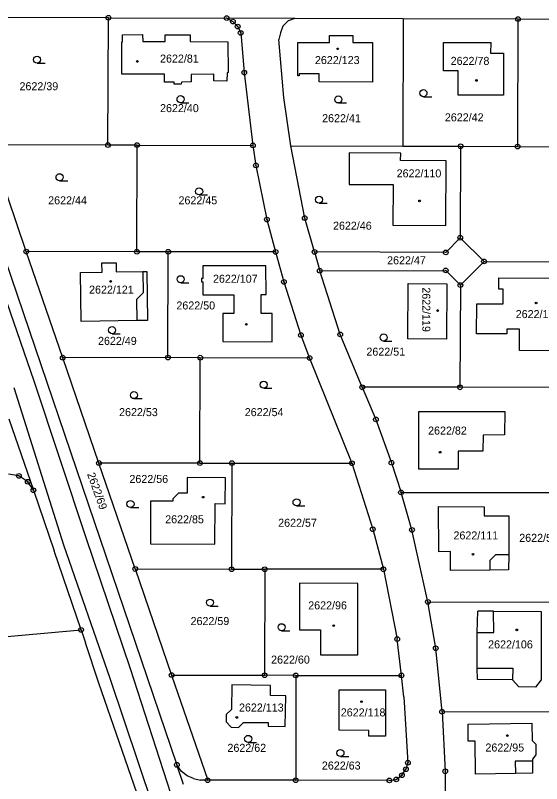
# Model space of a CAD drawing. Extents: x -736345 to -729997, y -1130177 to -1122501.
# Drawn here: x -734114.7 to -734002.9, y -1125902.8 to -1125739.6 of the extents above; entities that cross this region are included whole.
import ezdxf

# ---------------------------------------------------------------- set-up
doc = ezdxf.new("R2010")
doc.units = 0
for name, color, linetype in [('Vrstva 1', 7, 'Continuous'), ('Vrstva 18', 7, 'Continuous'), ('Vrstva 19', 7, 'Continuous'), ('Vrstva 25', 7, 'Continuous'), ('Vrstva 4', 7, 'Continuous')]:
    doc.layers.add(name, color=color, linetype=linetype)

msp = doc.modelspace()

# ---------------------------------------------------------------- linework, layer by layer
at = {"layer": 'Vrstva 1'}
for points in [[(-734094.92, -1125740.08), (-734126.23, -1125740.04)], [(-734095.04, -1125767.14), (-734094.92, -1125740.08)], [(-734094.92, -1125740.08), (-734069.81, -1125740.16)], [(-734069.81, -1125740.16), (-734068.48, -1125740.89)], [(-734055.33, -1125740.27), (-734069.81, -1125740.16)], [(-734055.33, -1125740.27), (-734056.77, -1125740.73)], [(-734032.34, -1125740.31), (-734055.33, -1125740.27)], [(-734032.34, -1125740.31), (-734032.38, -1125767.38)], [(-734007.98, -1125740.37), (-734032.34, -1125740.31)], [(-734007.98, -1125740.37), (-734008.04, -1125767.45)], [(-733971.15, -1125740.43), (-734007.98, -1125740.37)], [(-734068.48, -1125740.89), (-734067.48, -1125741.97)], [(-734067.48, -1125741.97), (-734066.84, -1125743.32)], [(-734057.87, -1125741.84), (-734058.39, -1125743.27)], [(-734056.77, -1125740.73), (-734057.87, -1125741.84)], [(-734066.84, -1125743.32), (-734066.08, -1125751.74)], [(-734058.39, -1125743.27), (-734058.72, -1125744.74)], [(-734092.08, -1125752.08), (-734092.09, -1125745.18)], [(-734092.09, -1125745.18), (-734091.9, -1125745.18)], [(-734091.9, -1125743.7), (-734087.66, -1125743.66)], [(-734091.9, -1125745.18), (-734091.9, -1125743.7)], [(-734087.66, -1125743.66), (-734087.63, -1125745.15)], [(-734087.63, -1125745.15), (-734082.89, -1125745.15)], [(-734082.89, -1125745.15), (-734082.89, -1125743.7)], [(-734082.89, -1125743.7), (-734077.59, -1125743.71)], [(-734077.59, -1125743.71), (-734077.6, -1125745.15)], [(-734077.6, -1125745.15), (-734069.54, -1125745.18)], [(-734069.54, -1125745.18), (-734069.49, -1125751.72)], [(-734057.69, -1125757.02), (-734058.72, -1125744.74)], [(-734047.96, -1125745.32), (-734047.96, -1125743.86)], [(-734047.96, -1125743.86), (-734043.05, -1125743.87)], [(-734043.05, -1125743.87), (-734043.05, -1125745.34)], [(-734054.69, -1125752.41), (-734054.69, -1125745.32)], [(-734054.69, -1125745.32), (-734047.96, -1125745.32)], [(-734043.05, -1125745.34), (-734038.84, -1125745.35)], [(-734038.84, -1125745.35), (-734038.85, -1125753.75)], [(-734023.8, -1125751.34), (-734023.78, -1125745.33)], [(-734023.78, -1125745.33), (-734013.76, -1125745.36)], [(-734013.76, -1125745.36), (-734013.77, -1125747.59)], [(-734131.94, -1125747.29), (-734080.38, -1125898.82)], [(-734013.77, -1125747.59), (-734011.03, -1125747.62)], [(-734011.03, -1125747.62), (-734011.05, -1125756.51)], [(-734069.72, -1125751.78), (-734069.75, -1125753.53)], [(-734069.49, -1125751.72), (-734069.72, -1125751.78)], [(-734066.08, -1125751.74), (-734064.26, -1125767.2)], [(-734020.69, -1125751.34), (-734023.8, -1125751.34)], [(-734020.68, -1125756.52), (-734020.69, -1125751.34)], [(-734083.04, -1125752.1), (-734092.08, -1125752.08)], [(-734083.03, -1125753.74), (-734083.04, -1125752.1)], [(-734077.36, -1125752.11), (-734077.37, -1125753.72)], [(-734072.55, -1125752.1), (-734077.36, -1125752.11)], [(-734072.56, -1125753.52), (-734072.55, -1125752.1)], [(-734054.41, -1125752.41), (-734054.69, -1125752.41)], [(-734050.19, -1125752.03), (-734054.41, -1125752.02)], [(-734054.41, -1125752.02), (-734054.41, -1125752.41)], [(-734050.19, -1125753.72), (-734050.19, -1125752.03)], [(-734080.96, -1125753.8), (-734083.03, -1125753.74)], [(-734080.96, -1125754.22), (-734080.96, -1125753.8)], [(-734079.46, -1125754.23), (-734080.96, -1125754.22)], [(-734079.42, -1125753.75), (-734079.46, -1125754.23)], [(-734077.37, -1125753.72), (-734079.42, -1125753.75)], [(-734069.75, -1125753.53), (-734072.56, -1125753.52)], [(-734038.85, -1125753.75), (-734050.19, -1125753.72)], [(-734011.05, -1125756.51), (-734020.68, -1125756.52)], [(-734056.17, -1125767.33), (-734057.69, -1125757.02)], [(-734112.36, -1125789.78), (-734120.11, -1125767.1)], [(-734095.04, -1125767.14), (-734120.11, -1125767.1)], [(-734088.85, -1125767.14), (-734095.04, -1125767.14)], [(-734088.88, -1125789.81), (-734088.85, -1125767.14)], [(-734088.85, -1125767.14), (-734064.26, -1125767.2)], [(-734064.26, -1125767.2), (-734063.62, -1125771.46)], [(-734053.24, -1125782.65), (-734056.17, -1125767.33)], [(-734056.17, -1125767.33), (-734032.38, -1125767.38)], [(-734032.38, -1125767.38), (-734020.17, -1125767.4)], [(-734020.17, -1125767.4), (-734020.23, -1125786.83)], [(-734020.17, -1125767.4), (-734008.04, -1125767.45)], [(-734008.04, -1125767.45), (-733957.96, -1125767.5)], [(-734043.78, -1125768.77), (-734043.82, -1125775.5)], [(-734032.87, -1125768.84), (-734043.78, -1125768.77)], [(-734032.88, -1125770.45), (-734032.87, -1125768.84)], [(-734023.18, -1125770.51), (-734032.88, -1125770.45)], [(-734023.28, -1125784.24), (-734023.18, -1125770.51)], [(-734063.62, -1125771.46), (-734061.27, -1125782.97)], [(-734043.82, -1125775.5), (-734034.48, -1125775.54)], [(-734034.48, -1125775.54), (-734034.51, -1125784.17)], [(-734051.16, -1125789.83), (-734053.24, -1125782.65)], [(-734061.27, -1125782.97), (-734059.43, -1125789.83)], [(-734034.51, -1125784.17), (-734023.28, -1125784.24)], [(-734020.23, -1125786.83), (-734023.3, -1125789.96)], [(-734015.18, -1125791.87), (-734020.23, -1125786.83)], [(-734104.63, -1125812.31), (-734112.36, -1125789.78)], [(-734088.88, -1125789.81), (-734112.36, -1125789.78)], [(-734082.23, -1125789.81), (-734088.88, -1125789.81)], [(-734082.28, -1125812.3), (-734082.23, -1125789.81)], [(-734059.43, -1125789.83), (-734082.23, -1125789.81)], [(-734059.43, -1125789.83), (-734057.66, -1125796.21)], [(-734023.3, -1125789.96), (-734051.16, -1125789.83)], [(-734051.16, -1125789.83), (-734050.04, -1125793.83)], [(-734100.71, -1125804.59), (-734100.85, -1125794.18), (-734096.28, -1125794.13), (-734096.31, -1125792.18), (-734093.29, -1125792.13), (-734093.26, -1125794.08), (-734087.63, -1125794.01)], [(-734020.19, -1125796.89), (-734015.18, -1125791.87)], [(-734015.18, -1125791.87), (-733965.42, -1125792.05)], [(-734087.63, -1125794.01), (-734086.8, -1125794), (-734086.64, -1125804.4), (-734088.87, -1125804.42)], [(-734061.47, -1125792.78), (-734074.88, -1125792.79)], [(-734074.88, -1125792.79), (-734074.88, -1125795.51)], [(-734061.46, -1125798.9), (-734061.47, -1125792.78)], [(-734050.04, -1125793.83), (-734023.32, -1125793.78)], [(-734045.7, -1125807.38), (-734050.04, -1125793.83)], [(-734023.32, -1125793.78), (-734020.19, -1125796.89)], [(-734074.88, -1125795.51), (-734075.13, -1125795.51)], [(-734075.13, -1125795.51), (-734075.13, -1125796.22)], [(-734012.05, -1125797.76), (-734012.04, -1125795.38)], [(-734012.04, -1125795.38), (-733995.71, -1125795.44)], [(-734075.13, -1125796.22), (-734074.88, -1125796.22)], [(-734074.88, -1125796.22), (-734074.88, -1125798.93)], [(-734057.66, -1125796.21), (-734054.04, -1125807.5)], [(-734023.05, -1125796.61), (-734023.14, -1125808.35), (-734031.35, -1125808.28), (-734031.29, -1125796.54), (-734023.05, -1125796.61)], [(-734020.19, -1125796.89), (-734020.28, -1125818.61)], [(-734074.88, -1125798.93), (-734068.31, -1125798.94)], [(-734068.31, -1125798.94), (-734068.31, -1125802.96)], [(-734062.5, -1125802.96), (-734062.5, -1125798.9)], [(-734062.5, -1125798.9), (-734061.46, -1125798.9)], [(-734011.1, -1125797.76), (-734012.05, -1125797.76)], [(-734011.11, -1125800.88), (-734011.1, -1125797.76)], [(-734016.74, -1125807.24), (-734016.71, -1125800.86)], [(-734016.71, -1125800.86), (-734011.11, -1125800.88)], [(-734068.31, -1125802.96), (-734070.61, -1125802.95)], [(-734070.61, -1125802.95), (-734070.6, -1125808.89)], [(-734060.18, -1125802.94), (-734062.5, -1125802.96)], [(-734060.18, -1125808.91), (-734060.18, -1125802.94)], [(-734088.87, -1125804.42), (-734100.71, -1125804.59)], [(-734010.37, -1125807.27), (-734016.74, -1125807.24)], [(-734007.63, -1125806.28), (-734010.37, -1125806.27)], [(-734010.37, -1125806.27), (-734010.37, -1125807.27)], [(-734007.65, -1125810.78), (-734007.63, -1125806.28)], [(-734070.6, -1125808.89), (-734060.18, -1125808.91)], [(-734054.04, -1125807.5), (-734052.2, -1125812.38)], [(-734041.02, -1125818.61), (-734045.7, -1125807.38)], [(-733993.77, -1125810.83), (-734007.65, -1125810.78)], [(-734082.28, -1125812.3), (-734104.63, -1125812.31)], [(-734096.94, -1125834.69), (-734104.63, -1125812.31)], [(-734075.44, -1125812.31), (-734082.28, -1125812.3)], [(-734075.48, -1125834.72), (-734075.44, -1125812.31)], [(-734052.2, -1125812.38), (-734075.44, -1125812.31)], [(-734052.2, -1125812.38), (-734043.22, -1125834.75)], [(-734020.28, -1125818.61), (-734041.02, -1125818.61)], [(-734041.02, -1125818.61), (-734038.12, -1125825.44)], [(-733973.75, -1125818.73), (-734020.28, -1125818.61)], [(-734029.04, -1125823.75), (-734010.77, -1125823.72)], [(-734029.04, -1125836.03), (-734029.04, -1125823.75)], [(-734010.77, -1125823.72), (-734010.8, -1125828.74)], [(-734116.04, -1125825.31), (-734110.85, -1125840.49)], [(-734038.12, -1125825.44), (-734034.83, -1125834.64)], [(-734015.39, -1125828.77), (-734015.43, -1125832.14)], [(-734010.8, -1125828.74), (-734015.39, -1125828.77)], [(-734020.65, -1125832.14), (-734020.67, -1125836.01)], [(-734015.43, -1125832.14), (-734020.65, -1125832.14)], [(-734089.23, -1125857.21), (-734096.94, -1125834.69)], [(-734075.48, -1125834.72), (-734096.94, -1125834.69)], [(-734075.48, -1125834.72), (-734068.71, -1125834.7)], [(-734068.71, -1125834.7), (-734068.76, -1125857.26)], [(-734068.71, -1125834.7), (-734043.22, -1125834.75)], [(-734043.22, -1125834.75), (-734038.8, -1125848.75)], [(-734034.83, -1125834.64), (-734032.8, -1125840.94)], [(-734020.67, -1125836.01), (-734029.04, -1125836.03)], [(-734113.92, -1125837.42), (-734116.13, -1125837.03)], [(-734112.05, -1125838.66), (-734113.92, -1125837.42)], [(-734078.21, -1125837.79), (-734078.22, -1125841.09)], [(-734070.08, -1125837.82), (-734078.21, -1125837.79)], [(-734070.1, -1125843.33), (-734070.08, -1125837.82)], [(-734110.85, -1125840.49), (-734112.05, -1125838.66)], [(-734110.85, -1125840.49), (-734106.44, -1125853.38)], [(-734080.04, -1125841.1), (-734081.22, -1125842.29)], [(-734078.22, -1125841.09), (-734080.04, -1125841.1)], [(-734030.47, -1125848.91), (-734032.8, -1125840.94)], [(-734032.8, -1125840.94), (-733996.71, -1125840.98)], [(-734081.22, -1125842.78), (-734086.02, -1125842.78)], [(-734086.02, -1125842.78), (-734086, -1125851.89)], [(-734081.22, -1125842.29), (-734081.22, -1125842.78)], [(-734072.32, -1125851.91), (-734072.28, -1125843.32)], [(-734072.28, -1125843.32), (-734070.1, -1125843.33)], [(-734024.82, -1125843.96), (-734015.13, -1125844)], [(-734024.78, -1125853.55), (-734024.82, -1125843.96)], [(-734015.13, -1125844), (-734015.13, -1125845.89)], [(-734015.13, -1125845.89), (-734009.92, -1125845.91)], [(-734009.92, -1125845.91), (-734009.94, -1125854.22)], [(-734038.8, -1125848.75), (-734036.53, -1125857.28)], [(-734027.09, -1125864.2), (-734030.47, -1125848.91)], [(-734086, -1125851.89), (-734072.32, -1125851.91)], [(-734100.71, -1125870.15), (-734106.44, -1125853.38)], [(-734022.29, -1125853.52), (-734024.78, -1125853.55)], [(-734022.3, -1125857.52), (-734022.29, -1125853.52)], [(-734009.94, -1125854.22), (-734010.01, -1125857.42)], [(-734089.23, -1125857.21), (-734068.76, -1125857.26)], [(-734089.23, -1125857.21), (-734081.5, -1125879.74)], [(-734068.76, -1125857.26), (-734061.72, -1125857.27)], [(-734061.72, -1125857.27), (-734061.75, -1125879.79)], [(-734036.53, -1125857.28), (-734061.72, -1125857.27)], [(-734036.53, -1125857.28), (-734033.61, -1125872.11)], [(-734013.94, -1125857.49), (-734022.3, -1125857.52)], [(-734010.01, -1125857.42), (-734013.94, -1125857.49)], [(-734054.33, -1125860.23), (-734054.35, -1125870.14)], [(-734041.95, -1125860.26), (-734054.33, -1125860.23)], [(-734041.98, -1125875.42), (-734041.95, -1125860.26)], [(-734025.43, -1125874.05), (-734027.09, -1125864.2)], [(-734027.09, -1125864.2), (-733996.41, -1125864.26)], [(-734016.6, -1125870.68), (-734016.51, -1125866.17)], [(-734013.19, -1125866.2), (-734016.51, -1125866.17)], [(-734013.19, -1125866.2), (-734003.05, -1125866.23)], [(-734003.05, -1125866.23), (-734003.01, -1125880.79)], [(-734151.91, -1125874.75), (-734100.71, -1125870.15)], [(-734100.71, -1125870.15), (-734099.77, -1125872.89)], [(-734054.35, -1125870.14), (-734049.91, -1125870.14)], [(-734049.91, -1125870.14), (-734049.91, -1125875.42)], [(-734016.6, -1125878.29), (-734016.6, -1125870.68)], [(-734032.71, -1125879.82), (-734033.61, -1125872.11)], [(-734096.95, -1125881.49), (-734099.77, -1125872.89)], [(-734024.09, -1125887.55), (-734025.43, -1125874.05)], [(-734049.91, -1125875.42), (-734041.98, -1125875.42)], [(-734016.58, -1125880.72), (-734016.6, -1125878.29)], [(-734081.5, -1125879.74), (-734061.75, -1125879.79)], [(-734081.5, -1125879.74), (-734073.85, -1125902.09)], [(-734055.14, -1125879.81), (-734061.75, -1125879.79)], [(-734055.14, -1125879.81), (-734055.15, -1125902.09)], [(-734055.14, -1125879.81), (-734032.71, -1125879.82)], [(-734032.19, -1125884.35), (-734032.71, -1125879.82)], [(-734009.14, -1125880.73), (-734016.58, -1125880.72)], [(-734007.82, -1125882.27), (-734009.14, -1125880.73)], [(-734086.35, -1125912.11), (-734096.95, -1125881.49)], [(-734068.74, -1125881.79), (-734068.82, -1125887.04)], [(-734060.48, -1125881.95), (-734068.74, -1125881.79)], [(-734060.52, -1125884.12), (-734060.48, -1125881.95)], [(-734004.22, -1125882.3), (-734007.82, -1125882.27)], [(-734003.01, -1125880.79), (-734004.22, -1125882.3)], [(-734045.95, -1125882.86), (-734036.09, -1125882.87), (-734036.09, -1125892.71), (-734039.61, -1125892.72), (-734039.62, -1125891.5), (-734045.95, -1125891.48), (-734045.95, -1125882.86)], [(-734057.26, -1125884.16), (-734060.52, -1125884.12)], [(-734057.38, -1125890.67), (-734057.26, -1125884.16)], [(-734032.19, -1125884.35), (-734031.34, -1125898.37)], [(-734068.82, -1125887.04), (-734069.91, -1125888.13)], [(-734069.91, -1125888.13), (-734069.93, -1125889.69)], [(-734024.09, -1125887.55), (-733991.66, -1125887.51)], [(-734024.09, -1125887.55), (-734023.41, -1125900.2)], [(-734069.93, -1125889.69), (-734068.85, -1125890.81)], [(-734067.28, -1125890.88), (-734066.23, -1125889.83)], [(-734066.23, -1125889.83), (-734061.03, -1125889.86)], [(-734061.03, -1125889.86), (-734061.04, -1125890.62)], [(-734018.57, -1125890.15), (-734005.02, -1125889.98)], [(-734018.52, -1125893.76), (-734018.57, -1125890.15)], [(-734005.02, -1125889.98), (-734004.97, -1125893.67)], [(-734068.85, -1125890.81), (-734067.28, -1125890.88)], [(-734061.04, -1125890.62), (-734057.38, -1125890.67)], [(-734017.09, -1125893.79), (-734018.52, -1125893.76)], [(-734016.97, -1125900.78), (-734017.09, -1125893.79)], [(-734004.97, -1125893.67), (-734004.19, -1125894.42)], [(-734004.19, -1125894.42), (-734004.18, -1125896.69)], [(-734004.18, -1125896.69), (-734004.88, -1125897.63)], [(-734031.34, -1125898.37), (-734031.77, -1125899.76)], [(-734004.88, -1125898.05), (-734004.91, -1125900.57)], [(-734004.88, -1125897.63), (-734004.88, -1125898.05)], [(-734078.96, -1125903), (-734080.38, -1125898.82)], [(-734079.4, -1125900.21), (-734080.38, -1125898.82)], [(-734078.19, -1125901.14), (-734079.4, -1125900.21)], [(-734032.6, -1125901.04), (-734031.77, -1125899.76)], [(-734023.41, -1125900.2), (-734023.46, -1125910.4)], [(-734076.83, -1125901.75), (-734078.19, -1125901.14)], [(-734076.83, -1125901.75), (-734075.38, -1125902.06)], [(-734035.27, -1125902.13), (-734033.81, -1125901.92)], [(-734033.81, -1125901.92), (-734032.6, -1125901.04)], [(-734008.5, -1125900.63), (-734016.97, -1125900.78)], [(-734004.91, -1125900.57), (-734008.5, -1125900.63)], [(-734073.85, -1125902.09), (-734075.38, -1125902.06)], [(-734055.15, -1125902.09), (-734073.85, -1125902.09)], [(-734035.27, -1125902.13), (-734055.15, -1125902.09)]]:
    msp.add_lwpolyline(points, dxfattribs=at)
at = {"layer": 'Vrstva 25'}
for points in [[(-734110.07, -1125749.74), (-734108.32, -1125749.74)], [(-734079.6, -1125758.14), (-734077.85, -1125758.14)], [(-734046.1, -1125758.19), (-734044.35, -1125758.19)], [(-734028.04, -1125756.86), (-734026.29, -1125756.86)], [(-734105.29, -1125774.72), (-734103.54, -1125774.72)], [(-734075.66, -1125777.73), (-734073.91, -1125777.73)], [(-734050.21, -1125779.49), (-734048.46, -1125779.49)], [(-734079.58, -1125796.39), (-734077.83, -1125796.39)], [(-734094.15, -1125807.21), (-734092.4, -1125807.21)], [(-734036.5, -1125808.77), (-734034.75, -1125808.77)], [(-734061.96, -1125818.8), (-734060.21, -1125818.8)], [(-734089.5, -1125821.01), (-734087.75, -1125821.01)], [(-734090.24, -1125844.15), (-734088.49, -1125844.15)], [(-734054.98, -1125843.79), (-734053.23, -1125843.79)], [(-734073.34, -1125865.1), (-734071.59, -1125865.1)], [(-734058.15, -1125870.33), (-734056.4, -1125870.33)], [(-734065.25, -1125894.06), (-734063.5, -1125894.06)], [(-734045.66, -1125897.05), (-734043.91, -1125897.05)]]:
    msp.add_lwpolyline(points, dxfattribs=at)
for centre, radius in [((-734094.92, -1125740.08), 0.5), ((-734094.92, -1125740.08), 0.032), ((-734069.81, -1125740.16), 0.5), ((-734069.81, -1125740.16), 0.032), ((-734007.98, -1125740.37), 0.5), ((-734007.98, -1125740.37), 0.032), ((-734068.48, -1125740.89), 0.5), ((-734068.48, -1125740.89), 0.032), ((-734067.48, -1125741.97), 0.5), ((-734067.48, -1125741.97), 0.032), ((-734066.84, -1125743.32), 0.5), ((-734066.84, -1125743.32), 0.032), ((-734046.26, -1125746.69), 0.175), ((-734110.07, -1125748.99), 0.75), ((-734088.77, -1125749.37), 0.175), ((-734066.08, -1125751.74), 0.5), ((-734066.08, -1125751.74), 0.032), ((-734016.79, -1125753.41), 0.175), ((-734079.6, -1125757.39), 0.75), ((-734046.1, -1125757.44), 0.75), ((-734028.04, -1125756.11), 0.75), ((-734095.04, -1125767.14), 0.5), ((-734095.04, -1125767.14), 0.032), ((-734088.85, -1125767.14), 0.5), ((-734088.85, -1125767.14), 0.032), ((-734064.26, -1125767.2), 0.5), ((-734064.26, -1125767.2), 0.032), ((-734020.17, -1125767.4), 0.5), ((-734020.17, -1125767.4), 0.032), ((-734008.04, -1125767.45), 0.5), ((-734008.04, -1125767.45), 0.032), ((-734063.62, -1125771.46), 0.5), ((-734063.62, -1125771.46), 0.032), ((-734105.29, -1125773.97), 0.75), ((-734075.66, -1125776.98), 0.75), ((-734050.21, -1125778.74), 0.75), ((-734028.87, -1125779), 0.175), ((-734061.27, -1125782.97), 0.5), ((-734053.24, -1125782.65), 0.5), ((-734053.24, -1125782.65), 0.032), ((-734061.27, -1125782.97), 0.032), ((-734020.23, -1125786.83), 0.5), ((-734020.23, -1125786.83), 0.032), ((-734112.36, -1125789.78), 0.5), ((-734088.88, -1125789.81), 0.5), ((-734082.23, -1125789.81), 0.5), ((-734059.43, -1125789.83), 0.5), ((-734051.16, -1125789.83), 0.5), ((-734112.36, -1125789.78), 0.032), ((-734088.88, -1125789.81), 0.032), ((-734082.23, -1125789.81), 0.032), ((-734059.43, -1125789.83), 0.032), ((-734051.16, -1125789.83), 0.032), ((-734023.3, -1125789.96), 0.5), ((-734023.3, -1125789.96), 0.032), ((-734015.18, -1125791.87), 0.5), ((-734015.18, -1125791.87), 0.032), ((-734050.04, -1125793.83), 0.5), ((-734050.04, -1125793.83), 0.032), ((-734023.32, -1125793.78), 0.5), ((-734023.32, -1125793.78), 0.032), ((-734079.58, -1125795.64), 0.75), ((-734057.66, -1125796.21), 0.5), ((-734094.46, -1125796.11), 0.175), ((-734057.66, -1125796.21), 0.032), ((-734020.19, -1125796.89), 0.5), ((-734020.19, -1125796.89), 0.032), ((-734004.11, -1125800.68), 0.175), ((-734025.03, -1125802.29), 0.175), ((-734065.63, -1125805.21), 0.175), ((-734094.15, -1125806.46), 0.75), ((-734054.04, -1125807.5), 0.5), ((-734045.7, -1125807.38), 0.5), ((-734036.5, -1125808.02), 0.75), ((-734054.04, -1125807.5), 0.032), ((-734045.7, -1125807.38), 0.032), ((-734104.63, -1125812.31), 0.5), ((-734082.28, -1125812.3), 0.5), ((-734075.44, -1125812.31), 0.5), ((-734052.2, -1125812.38), 0.5), ((-734104.63, -1125812.31), 0.032), ((-734082.28, -1125812.3), 0.032), ((-734075.44, -1125812.31), 0.032), ((-734052.2, -1125812.38), 0.032), ((-734061.96, -1125818.05), 0.75), ((-734041.02, -1125818.61), 0.5), ((-734041.02, -1125818.61), 0.032), ((-734020.28, -1125818.61), 0.5), ((-734020.28, -1125818.61), 0.032), ((-734089.5, -1125820.26), 0.75), ((-734038.12, -1125825.44), 0.5), ((-734038.12, -1125825.44), 0.032), ((-734024.5, -1125832.4), 0.175), ((-734096.94, -1125834.69), 0.5), ((-734096.94, -1125834.69), 0.032), ((-734075.48, -1125834.72), 0.5), ((-734075.48, -1125834.72), 0.032), ((-734068.71, -1125834.7), 0.5), ((-734068.71, -1125834.7), 0.032), ((-734043.22, -1125834.75), 0.5), ((-734043.22, -1125834.75), 0.032), ((-734034.83, -1125834.64), 0.5), ((-734034.83, -1125834.64), 0.032), ((-734113.92, -1125837.42), 0.5), ((-734113.92, -1125837.42), 0.032), ((-734112.05, -1125838.66), 0.5), ((-734112.05, -1125838.66), 0.032), ((-734110.85, -1125840.49), 0.5), ((-734110.85, -1125840.49), 0.032), ((-734032.8, -1125840.94), 0.5), ((-734032.8, -1125840.94), 0.032), ((-734090.24, -1125843.4), 0.75), ((-734074.81, -1125841.95), 0.175), ((-734054.98, -1125843.04), 0.75), ((-734038.8, -1125848.75), 0.5), ((-734038.8, -1125848.75), 0.032), ((-734030.47, -1125848.91), 0.5), ((-734030.47, -1125848.91), 0.032), ((-734017.53, -1125854.07), 0.175), ((-734089.23, -1125857.21), 0.5), ((-734089.23, -1125857.21), 0.032), ((-734068.76, -1125857.26), 0.5), ((-734068.76, -1125857.26), 0.032), ((-734061.72, -1125857.27), 0.5), ((-734061.72, -1125857.27), 0.032), ((-734036.53, -1125857.28), 0.5), ((-734036.53, -1125857.28), 0.032), ((-734073.34, -1125864.35), 0.75), ((-734027.09, -1125864.2), 0.5), ((-734027.09, -1125864.2), 0.032), ((-734058.15, -1125869.58), 0.75), ((-734047.09, -1125869.24), 0.175), ((-734100.71, -1125870.15), 0.5), ((-734100.71, -1125870.15), 0.032), ((-734008.21, -1125870.15), 0.175), ((-734033.61, -1125872.11), 0.5), ((-734033.61, -1125872.11), 0.032), ((-734025.43, -1125874.05), 0.5), ((-734025.43, -1125874.05), 0.032), ((-734081.5, -1125879.74), 0.5), ((-734081.5, -1125879.74), 0.032), ((-734061.75, -1125879.79), 0.5), ((-734061.75, -1125879.79), 0.032), ((-734055.14, -1125879.81), 0.5), ((-734055.14, -1125879.81), 0.032), ((-734032.71, -1125879.82), 0.5), ((-734032.71, -1125879.82), 0.032), ((-734041.19, -1125885.39), 0.175), ((-734024.09, -1125887.55), 0.5), ((-734067.67, -1125888.75), 0.175), ((-734024.09, -1125887.55), 0.032), ((-734065.25, -1125893.31), 0.75), ((-734010.23, -1125892.6), 0.175), ((-734045.66, -1125896.3), 0.75), ((-734080.38, -1125898.82), 0.5), ((-734031.34, -1125898.37), 0.5), ((-734031.34, -1125898.37), 0.032), ((-734080.38, -1125898.82), 0.032), ((-734031.77, -1125899.76), 0.5), ((-734031.77, -1125899.76), 0.032), ((-734023.41, -1125900.2), 0.5), ((-734023.41, -1125900.2), 0.032), ((-734073.85, -1125902.09), 0.5), ((-734055.15, -1125902.09), 0.5), ((-734035.27, -1125902.13), 0.5), ((-734033.81, -1125901.92), 0.5), ((-734033.81, -1125901.92), 0.032), ((-734032.6, -1125901.04), 0.5), ((-734032.6, -1125901.04), 0.032), ((-734073.85, -1125902.09), 0.032), ((-734055.15, -1125902.09), 0.032), ((-734035.27, -1125902.13), 0.032)]:
    msp.add_circle(centre, radius, dxfattribs=at)
at = {"layer": 'Vrstva 4'}
for points in [[(-734122.28, -1125783.91), (-734110.73, -1125817.26)], [(-734087.63, -1125794.01), (-734087.57, -1125798.51), (-734088.94, -1125799.98), (-734088.87, -1125804.42)], [(-734110.73, -1125817.26), (-734099.73, -1125850.51)], [(-734104.4, -1125852.13), (-734114.93, -1125818.74)], [(-734099.73, -1125850.51), (-734090.28, -1125878.32)], [(-734094.57, -1125880.5), (-734104.4, -1125852.13)], [(-734012.76, -1125854.21), (-734013.95, -1125855.38)], [(-734009.94, -1125854.22), (-734012.76, -1125854.21)], [(-734013.95, -1125855.38), (-734013.94, -1125857.49)], [(-734013.11, -1125870.71), (-734013.19, -1125866.2)], [(-734016.6, -1125870.68), (-734013.11, -1125870.71)], [(-734090.28, -1125878.32), (-734081.73, -1125904.81)], [(-734016.6, -1125878.29), (-734009.06, -1125878.3)], [(-734009.06, -1125878.3), (-734009.14, -1125880.73)], [(-734085.48, -1125907.47), (-734094.57, -1125880.5)], [(-734004.88, -1125898.05), (-734008.55, -1125898.04)], [(-734008.55, -1125898.04), (-734008.5, -1125900.63)]]:
    msp.add_lwpolyline(points, dxfattribs=at)

# ---------------------------------------------------------------- texts
at = {"layer": 'Vrstva 18'}
for s, p in [('2622/39', (-734113.8, -1125755.49)), ('2622/40', (-734083.96, -1125760.14)), ('2622/41', (-734049.55, -1125762.28)), ('2622/42', (-734023.49, -1125762.1)), ('2622/44', (-734107.71, -1125779.73)), ('2622/45', (-734080.04, -1125779.73)), ('2622/46', (-734047.24, -1125785.12)), ('2622/47', (-734035.75, -1125792.47)), ('2622/50', (-734080.49, -1125802.07)), ('2622/49', (-734097.128, -1125809.59)), ('2622/51', (-734040.15, -1125811.89)), ('2622/53', (-734092.66, -1125824.73)), ('2622/54', (-734065.98, -1125824.73)), ('2622/56', (-734090.46, -1125838.93)), ('2622/57', (-734058.88, -1125848.24)), ('2622/58', (-734007.7, -1125851.44)), ('2622/59', (-734077.48, -1125869.12)), ('2622/60', (-734060.38, -1125877.31)), ('2622/62', (-734069.65, -1125896.06)), ('2622/63', (-734049.6, -1125899.82))]:
    msp.add_text(s, height=1.7, dxfattribs=at).set_placement(p)
msp.add_text('2622/69', height=1.7, rotation=289.6023, dxfattribs=at).set_placement((-734099.475, -1125837.041))
at = {"layer": 'Vrstva 19'}
for s, p in [('2622/81', (-734083.96, -1125749.61)), ('2622/123', (-734051.079, -1125749.93)), ('2622/78', (-734022.26, -1125750.1)), ('2622/110', (-734033.73, -1125774)), ('2622/107', (-734072.72, -1125796.39)), ('2622/121', (-734099.029, -1125798.7)), ('2622/116', (-734008.45, -1125803.9)), ('2622/82', (-734027.05, -1125828.65)), ('2622/85', (-734082.87, -1125847.5)), ('2622/111', (-734021.66, -1125850.93)), ('2622/96', (-734052.5, -1125865.79)), ('2622/106', (-734014.3, -1125874.08)), ('2622/113', (-734067.2, -1125887.49)), ('2622/118', (-734045.589, -1125888.53)), ('2622/95', (-734014.88, -1125895.99))]:
    msp.add_text(s, height=1.7, dxfattribs=at).set_placement(p)
msp.add_text('2622/119', height=1.7, rotation=270.00215, dxfattribs=at).set_placement((-734028.28, -1125797.361))

doc.saveas('drawing.dxf')
